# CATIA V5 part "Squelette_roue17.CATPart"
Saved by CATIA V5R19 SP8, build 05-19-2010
Part number: Squelette_roue17
Bounding box of the stored display mesh (mm): x -15 to 5, y 0 to 0, z 0 to 30
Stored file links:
  G:\EU_thinkMotion\CFAO_2010\MMS_groupe2\MMS_groupe2\A reprendre\jcauchy\Squelette_roue17.CATPart
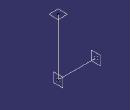
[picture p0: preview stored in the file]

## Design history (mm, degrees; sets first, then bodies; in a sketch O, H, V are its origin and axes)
Parameters
  Longueurfixation_roue17 = 20 mm
  Rayonroue_roue17 = 30 mm
Set1
  Point1: (5 {= Longueurfixation_roue17 -15mm}, 0, 0)
  Point2: (-15, 0, 0)
  Line1: type PtPt, FirstPoint Point1, SecondPoint Point2
  Point3: type OnCurve, Support Line1, RefPoint Point2, Length -20 {= -Longueurfixation_roue17}
  Line2: type Angle, RefPoint Point3, Curve Line1, Support zx-plane, Start 0, End 30 {= Rayonroue_roue17}, Angle 90
  Plane1: type Normal, Curve Line2, RefPoint vertex of Line2
  Plane2: type Normal, Curve Line1, RefPoint Point2
  Plane3: type Normal, Curve Line1, RefPoint Point1
Body1 (main body)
